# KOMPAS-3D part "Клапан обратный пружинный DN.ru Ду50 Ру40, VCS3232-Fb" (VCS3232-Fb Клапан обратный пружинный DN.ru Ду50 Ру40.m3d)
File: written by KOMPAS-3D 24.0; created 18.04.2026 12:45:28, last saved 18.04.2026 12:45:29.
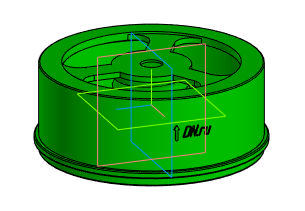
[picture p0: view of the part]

Document properties: Автор: 712; Полное имя файла: C:\Users\712\Desktop\Новая папка (4)\VCS3232-Fb Клапан обратный пружинный DN.ru Ду50 Ру40.m3d

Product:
- Component: Пружина 1086-0966 ГОСТ 18793-80  | qty 1  | additional columns: 3953604318-4147491677-0; Деталь; Пользователь Windows; c; Шероховатость не задана; Да; Сталь 10  ГОСТ 1050-88; source file: Деталь_3.m3d
- Body: Тело 1  | qty 1
    Масса: 0.725562
- Part/product: Клапан обратный пружинный DN.ru Ду50 Ру40  | designation VCS3232-Fb
    Масса: 0.94
    Раздел спецификации: Прочие изделия
    Примечание: D100-03891
    additional columns: 071bd168-1a06-425c-849c-e99e84a96128; Деталь; 712; c; Шероховатость не задана; Да

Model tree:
1. Операция без истории:2

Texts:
  VCS3232-Fb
